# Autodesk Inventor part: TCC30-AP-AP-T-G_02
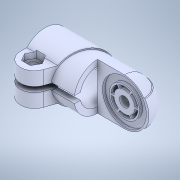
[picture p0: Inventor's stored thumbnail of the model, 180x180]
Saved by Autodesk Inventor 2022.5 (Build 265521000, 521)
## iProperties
Created: 2023-09
Part Number: TCC30-AP-AP-T-G_02
Material: 一般
Document SubType Name: Modeling
Designer: ImaoCorp
Density: 1 g/cm^3
Appearance: 既定
Author: ImaoCorp
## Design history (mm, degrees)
feature "TCC30-AP-AP-T-G_02"
node "ソリッド1"
